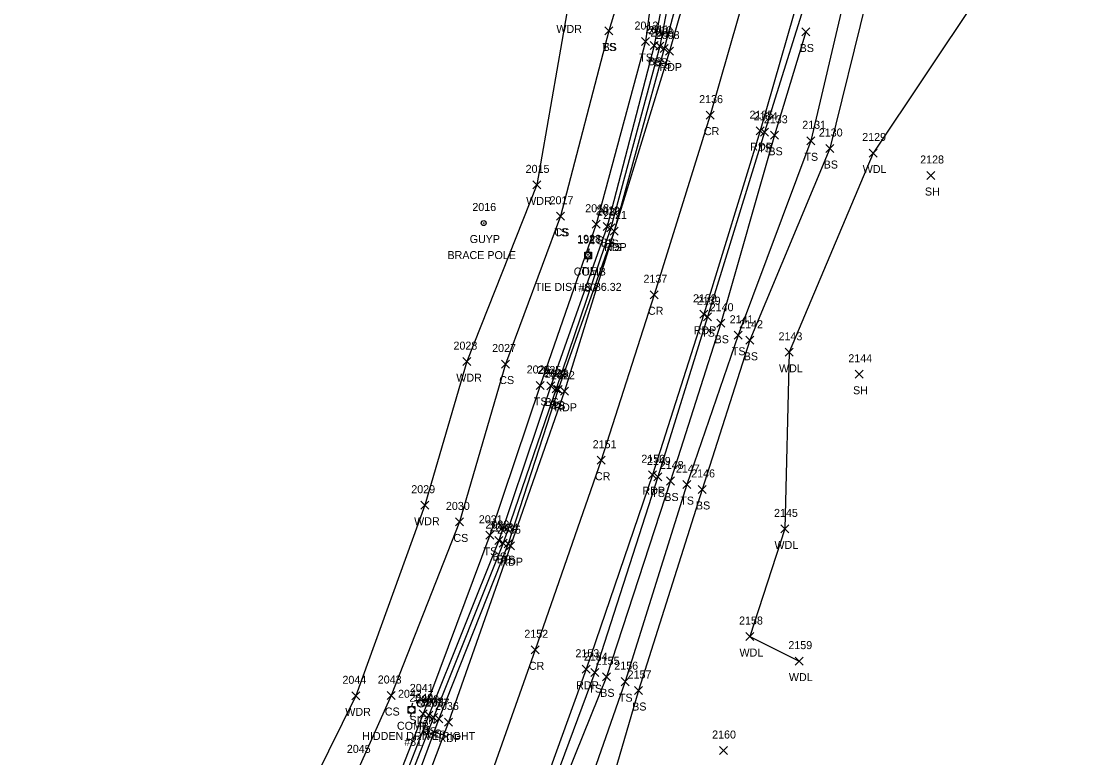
# Model space of a CAD drawing. Extents: x 1678863 to 1683592, y 407783 to 418211.
# Drawn here: x 1680931.7 to 1681197.9, y 416455.1 to 416639 of the extents above; entities that cross this region are included whole.
import ezdxf

# ---------------------------------------------------------------- set-up
doc = ezdxf.new("R2010")
doc.units = 0
for name, color, linetype in [('C_A', 7, 'Continuous'), ('C_C', 7, 'Continuous'), ('C_I', 7, 'Continuous'), ('CBP', 7, 'Continuous'), ('L_A', 7, 'Continuous'), ('L_I', 7, 'Continuous'), ('L_TIC', 7, 'Continuous'), ('LAWA', 7, 'Continuous'), ('LELB', 7, 'Continuous'), ('P_A', 7, 'Continuous'), ('P_I', 7, 'Continuous'), ('P_TIC', 7, 'Continuous'), ('PET', 7, 'Continuous'), ('PRC', 7, 'Continuous'), ('S_A', 7, 'Continuous'), ('S_C', 7, 'Continuous'), ('S_I', 7, 'Continuous'), ('SSGN', 7, 'Continuous'), ('U_A', 7, 'Continuous'), ('U_C', 7, 'Continuous'), ('U_I', 7, 'Continuous'), ('UP', 7, 'Continuous'), ('UPGW', 7, 'Continuous')]:
    doc.layers.add(name, color=color, linetype=linetype)

msp = doc.modelspace()

# ---------------------------------------------------------------- linework, layer by layer
at = {"layer": 'CBP'}
for radius in [0.625, 0.0833]:
    msp.add_circle((1681073.29, 416580.64), radius, dxfattribs=at)
at = {"layer": 'L_TIC'}
for points in [[(1681077.49, 416635.56), (1681079.49, 416637.56)], [(1681079.49, 416635.56), (1681077.49, 416637.56)], [(1681077.49, 416635.56), (1681079.49, 416637.56)], [(1681079.49, 416635.56), (1681077.49, 416637.56)], [(1681126.73, 416635.31), (1681128.73, 416637.31)], [(1681128.73, 416635.31), (1681126.73, 416637.31)], [(1681086.69, 416632.91), (1681088.69, 416634.91)], [(1681088.69, 416632.91), (1681086.69, 416634.91)], [(1681088.82, 416631.97), (1681090.82, 416633.97)], [(1681090.82, 416631.97), (1681088.82, 416633.97)], [(1681090.25, 416631.74), (1681092.25, 416633.74)], [(1681092.25, 416631.74), (1681090.25, 416633.74)], [(1681091.29, 416631.17), (1681093.29, 416633.17)], [(1681093.29, 416631.17), (1681091.29, 416633.17)], [(1681116.39, 416610.26), (1681118.39, 416612.26)], [(1681118.39, 416610.26), (1681116.39, 416612.26)], [(1681118.93, 416609.51), (1681120.93, 416611.51)], [(1681120.93, 416609.51), (1681118.93, 416611.51)], [(1681127.95, 416608.13), (1681129.95, 416610.13)], [(1681129.95, 416608.13), (1681127.95, 416610.13)], [(1681132.74, 416606.2), (1681134.74, 416608.2)], [(1681134.74, 416606.2), (1681132.74, 416608.2)], [(1681132.74, 416606.2), (1681134.74, 416608.2)], [(1681134.74, 416606.2), (1681132.74, 416608.2)], [(1681143.5, 416605.08), (1681145.5, 416607.08)], [(1681145.5, 416605.08), (1681143.5, 416607.08)], [(1681157.97, 416599.46), (1681159.97, 416601.46)], [(1681159.97, 416599.46), (1681157.97, 416601.46)], [(1681059.5, 416597.12), (1681061.5, 416599.12)], [(1681061.5, 416597.12), (1681059.5, 416599.12)], [(1681065.47, 416589.28), (1681067.47, 416591.28)], [(1681067.47, 416589.28), (1681065.47, 416591.28)], [(1681065.47, 416589.28), (1681067.47, 416591.28)], [(1681067.47, 416589.28), (1681065.47, 416591.28)], [(1681074.38, 416587.29), (1681076.38, 416589.29)], [(1681076.38, 416587.29), (1681074.38, 416589.29)], [(1681077.07, 416586.72), (1681079.07, 416588.72)], [(1681079.07, 416586.72), (1681077.07, 416588.72)], [(1681077.98, 416586.43), (1681079.98, 416588.43)], [(1681079.98, 416586.43), (1681077.98, 416588.43)], [(1681078.85, 416585.59), (1681080.85, 416587.59)], [(1681080.85, 416585.59), (1681078.85, 416587.59)], [(1681102.18, 416564.19), (1681104.18, 416566.19)], [(1681104.18, 416564.19), (1681102.18, 416566.19)], [(1681105.49, 416562.56), (1681107.49, 416564.56)], [(1681107.49, 416562.56), (1681105.49, 416564.56)], [(1681109.82, 416559.56), (1681111.82, 416561.56)], [(1681111.82, 416559.56), (1681109.82, 416561.56)], [(1681112.76, 416558.31), (1681114.76, 416560.31)], [(1681114.76, 416558.31), (1681112.76, 416560.31)], [(1681122.59, 416555.3), (1681124.59, 416557.3)], [(1681124.59, 416555.3), (1681122.59, 416557.3)], [(1681042.04, 416552.97), (1681044.04, 416554.97)], [(1681044.04, 416552.97), (1681042.04, 416554.97)], [(1681051.69, 416552.37), (1681053.69, 416554.37)], [(1681053.69, 416552.37), (1681051.69, 416554.37)], [(1681140.02, 416549.82), (1681142.02, 416551.82)], [(1681142.02, 416549.82), (1681140.02, 416551.82)], [(1681060.37, 416547.02), (1681062.37, 416549.02)], [(1681062.37, 416547.02), (1681060.37, 416549.02)], [(1681063.01, 416546.9), (1681065.01, 416548.9)], [(1681065.01, 416546.9), (1681063.01, 416548.9)], [(1681064.33, 416546.21), (1681066.33, 416548.21)], [(1681066.33, 416546.21), (1681064.33, 416548.21)], [(1681064.82, 416546), (1681066.82, 416548)], [(1681066.82, 416546), (1681064.82, 416548)], [(1681089.71, 416524.17), (1681091.71, 416526.17)], [(1681091.71, 416524.17), (1681089.71, 416526.17)], [(1681092.93, 416523.16), (1681094.93, 416525.16)], [(1681094.93, 416523.16), (1681092.93, 416525.16)], [(1681096.95, 416522.26), (1681098.95, 416524.26)], [(1681098.95, 416522.26), (1681096.95, 416524.26)], [(1681100.82, 416521.05), (1681102.82, 416523.05)], [(1681102.82, 416521.05), (1681100.82, 416523.05)], [(1681031.51, 416517.11), (1681033.51, 416519.11)], [(1681033.51, 416517.11), (1681031.51, 416519.11)], [(1681040.24, 416512.94), (1681042.24, 416514.94)], [(1681042.24, 416512.94), (1681040.24, 416514.94)], [(1681047.8, 416509.6), (1681049.8, 416511.6)], [(1681049.8, 416509.6), (1681047.8, 416511.6)], [(1681121.46, 416511.19), (1681123.46, 416513.19)], [(1681123.46, 416511.19), (1681121.46, 416513.19)], [(1681050.02, 416508.29), (1681052.02, 416510.29)], [(1681052.02, 416508.29), (1681050.02, 416510.29)], [(1681051.09, 416507.6), (1681053.09, 416509.6)], [(1681053.09, 416507.6), (1681051.09, 416509.6)], [(1681052.32, 416507.48), (1681054.32, 416509.48)], [(1681054.32, 416507.48), (1681052.32, 416509.48)], [(1681112.73, 416484.31), (1681114.73, 416486.31)], [(1681114.73, 416484.31), (1681112.73, 416486.31)], [(1681125.06, 416478.17), (1681127.06, 416480.17)], [(1681127.06, 416478.17), (1681125.06, 416480.17)], [(1681073.97, 416475.31), (1681075.97, 416477.31)], [(1681075.97, 416475.31), (1681073.97, 416477.31)], [(1681076.92, 416474.25), (1681078.92, 416476.25)], [(1681078.92, 416474.25), (1681076.92, 416476.25)], [(1681081.61, 416473.04), (1681083.61, 416475.04)], [(1681083.61, 416473.04), (1681081.61, 416475.04)], [(1681014.3, 416469.5), (1681016.3, 416471.5)], [(1681016.3, 416469.5), (1681014.3, 416471.5)], [(1681023.11, 416469.58), (1681025.11, 416471.58)], [(1681025.11, 416469.58), (1681023.11, 416471.58)], [(1681084.89, 416470.83), (1681086.89, 416472.83)], [(1681086.89, 416470.83), (1681084.89, 416472.83)], [(1681031.11, 416465.02), (1681033.11, 416467.02)], [(1681033.11, 416465.02), (1681031.11, 416467.02)], [(1681032.52, 416464.65), (1681034.52, 416466.65)], [(1681034.52, 416464.65), (1681032.52, 416466.65)], [(1681033.7, 416464.08), (1681035.7, 416466.08)], [(1681035.7, 416464.08), (1681033.7, 416466.08)], [(1681035.07, 416463.79), (1681037.07, 416465.79)], [(1681037.07, 416463.79), (1681035.07, 416465.79)], [(1681106.14, 416455.84), (1681108.14, 416457.84)], [(1681108.14, 416455.84), (1681106.14, 416457.84)]]:
    msp.add_lwpolyline(points, dxfattribs=at)
at = {"layer": 'LAWA'}
for points in [[(1681123.87, 416850.36), (1681112.64, 416799.22), (1681096.75, 416747.49), (1681084.37, 416698.19), (1681077.36, 416674.66), (1681068.03, 416641.07), (1681060.5, 416598.12), (1681043.04, 416553.97), (1681032.51, 416518.11), (1681015.3, 416470.5), (1680994.93, 416429.19), (1680981.71, 416387.43), (1680969.09, 416365.63), (1680956.12, 416364.06)], [(1681197.88, 416804.7), (1681183.57, 416753.88), (1681190.27, 416722.43), (1681186.67, 416700.64), (1681165.75, 416661.66), (1681170.52, 416645), (1681144.5, 416606.08), (1681123.59, 416556.3), (1681122.46, 416512.19), (1681113.73, 416485.31), (1681126.06, 416479.17)]]:
    msp.add_lwpolyline(points, dxfattribs=at)
at = {"layer": 'LELB'}
for points in [[(1681156.02, 416991.73), (1681158.77, 416971.49), (1681161.75, 416953.98), (1681162.32, 416941.7), (1681158.74, 416923.13), (1681154.13, 416896.13), (1681147.11, 416869.12), (1681139.06, 416835.21), (1681130.14, 416794.31), (1681117.24, 416738.31), (1681106.01, 416695.36), (1681091.21, 416662.1), (1681090.98, 416658.87), (1681087.69, 416633.91), (1681075.38, 416588.29), (1681061.37, 416548.02), (1681048.8, 416510.6), (1681032.11, 416466.02), (1681014.69, 416421.51), (1680996.26, 416391.39), (1680989.28, 416368.73)], [(1681149.59, 416868.75), (1681142.29, 416833.77), (1681132.86, 416793.93), (1681119.42, 416737.18), (1681108.02, 416695.19), (1681098.81, 416668.5), (1681096.71, 416664.36), (1681094.64, 416660.46), (1681094.42, 416657.6), (1681089.82, 416632.97), (1681078.07, 416587.72), (1681064.01, 416547.9), (1681051.02, 416509.29), (1681033.52, 416465.65), (1681016.06, 416420.72), (1681000.74, 416389.34), (1680998.23, 416385.31), (1680994.64, 416376.69), (1680989.07, 416359.69), (1680992.46, 416359.07)], [(1681150.8, 416868.4), (1681143.7, 416833.38), (1681134.26, 416793.51), (1681120.67, 416736.84), (1681109.84, 416694.34), (1681100.61, 416667.6), (1681097.91, 416664.11), (1681097.08, 416660.69), (1681095.87, 416657.34), (1681091.25, 416632.74), (1681078.98, 416587.43), (1681065.33, 416547.21), (1681052.09, 416508.6), (1681034.7, 416465.08), (1681017.14, 416420.01), (1681002.48, 416388.48), (1680999.77, 416381.75), (1680997.06, 416375.63), (1680992.46, 416359.07)], [(1681151.67, 416868.54), (1681144.5, 416832.96), (1681135.35, 416792.9), (1681121.88, 416736.5), (1681110.76, 416694.17), (1681101.65, 416666.79), (1681092.29, 416632.17), (1681079.85, 416586.59), (1681065.82, 416547), (1681053.32, 416508.48), (1681036.07, 416464.79), (1681019.24, 416419.35), (1681003.42, 416376.29), (1680994.23, 416357.71)], [(1681183.55, 416833.63), (1681182.26, 416826.66), (1681180.25, 416810.78), (1681169.29, 416761.59), (1681161.1, 416720.62), (1681142.83, 416670.76), (1681140.44, 416656.68), (1681135.09, 416652.62), (1681137.22, 416644.16), (1681128.95, 416609.13), (1681110.82, 416560.56), (1681097.95, 416523.26), (1681082.61, 416474.04), (1681065.03, 416423.77), (1681042.03, 416376.09), (1681025.29, 416329.55), (1681005.26, 416289.72), (1680988.66, 416250.32), (1680971.75, 416212.59), (1680955.51, 416173.95), (1680940.89, 416151.62), (1680938.9, 416140.82), (1680934.47, 416141.15), (1680931.74, 416141.56)], [(1681176.14, 416832.62), (1681170.47, 416807.9), (1681160.43, 416764.66), (1681148.59, 416720.54), (1681137.34, 416672.66), (1681130.15, 416651.97), (1681117.39, 416611.26), (1681103.18, 416565.19), (1681090.71, 416525.17), (1681074.97, 416476.31), (1681056.64, 416426.82), (1681038.03, 416377.84), (1681018.75, 416331.61)], [(1681165.97, 416718.74), (1681148.66, 416668.7), (1681146.23, 416653.37), (1681141.68, 416649.74), (1681142.8, 416644.03), (1681133.74, 416607.2)], [(1681096.41, 416695.15), (1681086.76, 416663.72), (1681078.49, 416636.56)], [(1681078.49, 416636.56), (1681066.47, 416590.28)], [(1681127.73, 416636.31), (1681119.93, 416610.51), (1681106.49, 416563.56), (1681093.93, 416524.16), (1681077.92, 416475.25), (1681058.1, 416426.11), (1681040.38, 416376.76), (1681020.53, 416330.9)], [(1681133.74, 416607.2), (1681113.76, 416559.31), (1681101.82, 416522.05), (1681085.89, 416471.83), (1681071.19, 416421.26), (1681051.86, 416373.86), (1681035.51, 416329.96), (1681028.19, 416324.2), (1681022.12, 416304.25), (1681026.28, 416298.9), (1681016.09, 416285.94), (1681000.34, 416247.72), (1680995.54, 416236.51), (1680975.32, 416181.38), (1680956.88, 416150.62)], [(1681066.47, 416590.28), (1681052.69, 416553.37), (1681041.24, 416513.94), (1681024.11, 416470.58), (1681016.4, 416453.26), (1681011.7, 416442.37), (1681008.55, 416423.6)]]:
    msp.add_lwpolyline(points, dxfattribs=at)
at = {"layer": 'P_TIC'}
for points in [[(1681092.64, 416630.55), (1681094.64, 416632.55)], [(1681094.64, 416630.55), (1681092.64, 416632.55)], [(1681102.82, 416614.54), (1681104.82, 416616.54)], [(1681104.82, 416614.54), (1681102.82, 416616.54)], [(1681115.34, 416610.65), (1681117.34, 416612.65)], [(1681117.34, 416610.65), (1681115.34, 416612.65)], [(1681078.85, 416585.59), (1681080.85, 416587.59)], [(1681080.85, 416585.59), (1681078.85, 416587.59)], [(1681088.85, 416569.67), (1681090.85, 416571.67)], [(1681090.85, 416569.67), (1681088.85, 416571.67)], [(1681101.21, 416564.8), (1681103.21, 416566.8)], [(1681103.21, 416564.8), (1681101.21, 416566.8)], [(1681066.41, 416545.57), (1681068.41, 416547.57)], [(1681068.41, 416545.57), (1681066.41, 416547.57)], [(1681075.6, 416528.35), (1681077.6, 416530.35)], [(1681077.6, 416528.35), (1681075.6, 416530.35)], [(1681088.4, 416524.72), (1681090.4, 416526.72)], [(1681090.4, 416524.72), (1681088.4, 416526.72)], [(1681052.93, 416507), (1681054.93, 416509)], [(1681054.93, 416507), (1681052.93, 416509)], [(1681059.09, 416480.99), (1681061.09, 416482.99)], [(1681061.09, 416480.99), (1681059.09, 416482.99)], [(1681071.85, 416476.14), (1681073.85, 416478.14)], [(1681073.85, 416476.14), (1681071.85, 416478.14)], [(1681037.48, 416462.96), (1681039.48, 416464.96)], [(1681039.48, 416462.96), (1681037.48, 416464.96)]]:
    msp.add_lwpolyline(points, dxfattribs=at)
at = {"layer": 'PET'}
for points in [[(1681153.18, 416868.37), (1681145.34, 416832.84), (1681136.15, 416792.61), (1681122.35, 416736.31), (1681111.4, 416694.04), (1681103.69, 416666.47), (1681093.64, 416631.55), (1681079.85, 416586.59), (1681067.41, 416546.57), (1681053.93, 416508), (1681038.48, 416463.96), (1681021.16, 416418.05), (1681004.81, 416375.74), (1680996.01, 416353.71), (1680982.81, 416321.51)], [(1681179.13, 416866.45), (1681171.86, 416831.02), (1681167.77, 416808.05), (1681157.66, 416765.3), (1681146.92, 416720.99), (1681134.47, 416674.25), (1681128.07, 416652.5), (1681116.34, 416611.65), (1681102.21, 416565.8), (1681089.4, 416525.72), (1681072.85, 416477.14), (1681054.83, 416427.43), (1681035.74, 416378.53), (1681017.06, 416332.68)]]:
    msp.add_lwpolyline(points, dxfattribs=at)
at = {"layer": 'PRC'}
msp.add_lwpolyline([(1681167.36, 416870.15), (1681159.37, 416832.34), (1681154.72, 416812.12), (1681150.38, 416792.5), (1681145.13, 416769.7), (1681134.02, 416724.02), (1681121.77, 416677.97), (1681115.56, 416656.52), (1681103.82, 416615.54), (1681089.85, 416570.67), (1681076.6, 416529.35), (1681060.09, 416481.99), (1681042.51, 416432.25), (1681023.42, 416383.55), (1681004.96, 416337.97)], dxfattribs=at)
at = {"layer": 'SSGN'}
for p, q in [((1681029.94, 416469.33), (1681033.27, 416469.33)), ((1681031.58, 416468.5), (1681031.58, 416468.5))]:
    msp.add_line(p, q, dxfattribs=at)
msp.add_circle((1681031.58, 416468.5), 0.833, dxfattribs=at)
at = {"layer": 'UP'}
for p, q in [((1681072.52, 416579.63), (1681072.52, 416581.3)), ((1681072.52, 416581.3), (1681074.18, 416581.3)), ((1681073.6, 416582.13), (1681073.35, 416581.3)), ((1681074.18, 416581.3), (1681074.18, 416579.63)), ((1681074.18, 416579.63), (1681072.52, 416579.63)), ((1681073.1, 416578.8), (1681073.35, 416579.63)), ((1681073.35, 416580.47), (1681073.35, 416580.47)), ((1681028.35, 416466.19), (1681028.35, 416467.86)), ((1681028.35, 416467.86), (1681030.02, 416467.86)), ((1681030.02, 416466.19), (1681028.35, 416466.19)), ((1681028.93, 416465.36), (1681029.18, 416466.19)), ((1681029.43, 416468.69), (1681029.18, 416467.86)), ((1681029.18, 416467.02), (1681029.18, 416467.02)), ((1681030.02, 416467.86), (1681030.02, 416466.19))]:
    msp.add_line(p, q, dxfattribs=at)
for centre in [(1681073.35, 416580.47), (1681029.18, 416467.02)]:
    msp.add_circle(centre, 0.833, dxfattribs=at)
at = {"layer": 'UPGW'}
for radius in [0.625, 0.0833]:
    msp.add_circle((1681047.24, 416588.59), radius, dxfattribs=at)

# ---------------------------------------------------------------- texts
at = {"layer": 'C_A'}
msp.add_text('TIE', height=2, dxfattribs=at).set_placement((1681071.37, 416575.64))
at = {"layer": 'C_C'}
msp.add_text('TIE DIST IS 86.32', height=2, dxfattribs=at).set_placement((1681060, 416571.64))
at = {"layer": 'C_I'}
msp.add_text('1928', height=2, dxfattribs=at).set_placement((1681070.6, 416583.64))
at = {"layer": 'L_A'}
for s, p in [('WDR', (1681065.4, 416636.07)), ('TS', (1681076.9, 416631.56)), ('BS', (1681076.93, 416631.56)), ('BS', (1681126.17, 416631.31)), ('TS', (1681086.1, 416628.91)), ('BS', (1681088.26, 416627.97)), ('BS', (1681089.69, 416627.74)), ('TS', (1681090.7, 416627.17)), ('TS', (1681115.8, 416606.26)), ('BS', (1681118.37, 416605.51)), ('TS', (1681127.36, 416604.13)), ('BS', (1681132.18, 416602.2)), ('BS', (1681132.18, 416602.2)), ('WDL', (1681141.92, 416601.08)), ('SH', (1681157.46, 416595.46)), ('WDR', (1681057.86, 416593.12)), ('TS', (1681064.88, 416585.28)), ('CS', (1681064.92, 416585.28)), ('TS', (1681073.79, 416583.29)), ('BS', (1681076.51, 416582.72)), ('BS', (1681077.42, 416582.43)), ('TS', (1681078.26, 416581.59)), ('TS', (1681101.59, 416560.19)), ('BS', (1681104.93, 416558.56)), ('TS', (1681109.23, 416555.56)), ('BS', (1681112.2, 416554.31)), ('WDL', (1681121.01, 416551.3)), ('WDR', (1681040.4, 416548.97)), ('CS', (1681051.13, 416548.37)), ('SH', (1681139.51, 416545.82)), ('TS', (1681059.78, 416543.02)), ('BS', (1681062.45, 416542.9)), ('BS', (1681063.77, 416542.21)), ('TS', (1681064.23, 416542)), ('TS', (1681089.12, 416520.17)), ('BS', (1681092.37, 416519.16)), ('TS', (1681096.36, 416518.26)), ('BS', (1681100.26, 416517.05)), ('WDR', (1681029.87, 416513.11)), ('CS', (1681039.68, 416508.94)), ('WDL', (1681119.88, 416507.19)), ('TS', (1681047.21, 416505.6)), ('BS', (1681049.46, 416504.29)), ('BS', (1681050.53, 416503.6)), ('TS', (1681051.73, 416503.48)), ('WDL', (1681111.15, 416480.31)), ('WDL', (1681123.48, 416474.17)), ('TS', (1681073.38, 416471.31)), ('BS', (1681076.36, 416470.25)), ('TS', (1681081.02, 416469.04)), ('BS', (1681084.33, 416466.83)), ('WDR', (1681012.67, 416465.5)), ('CS', (1681022.55, 416465.58)), ('TS', (1681030.52, 416461.02)), ('BS', (1681031.96, 416460.65)), ('BS', (1681033.14, 416460.08)), ('TS', (1681034.48, 416459.79))]:
    msp.add_text(s, height=2, dxfattribs=at).set_placement(p)
at = {"layer": 'L_I'}
for s, p in [('2012', (1681084.92, 416636.91)), ('2011', (1681087.62, 416635.97)), ('2010', (1681088.39, 416635.74)), ('2009', (1681088.87, 416635.17)), ('2134', (1681114.7, 416614.26)), ('2133', (1681117.24, 416613.51)), ('2131', (1681126.82, 416612.13)), ('2130', (1681130.96, 416610.2)), ('2130', (1681130.96, 416610.2)), ('2129', (1681141.8, 416609.08)), ('2128', (1681156.28, 416603.46)), ('2015', (1681057.72, 416601.12)), ('2017', (1681063.7, 416593.28)), ('2017', (1681063.7, 416593.28)), ('2018', (1681072.61, 416591.29)), ('2019', (1681075.29, 416590.72)), ('2020', (1681075.55, 416590.43)), ('2021', (1681077.07, 416589.59)), ('2139', (1681100.48, 416568.19)), ('2140', (1681103.71, 416566.56)), ('2141', (1681108.69, 416563.56)), ('2142', (1681111.07, 416562.31)), ('2143', (1681120.9, 416559.3)), ('2028', (1681039.7, 416556.97)), ('2027', (1681049.35, 416556.37)), ('2144', (1681138.33, 416553.82)), ('2026', (1681057.98, 416551.02)), ('2025', (1681060.67, 416550.9)), ('2024', (1681061.99, 416550.21)), ('2023', (1681062.48, 416550)), ('2149', (1681088.01, 416528.17)), ('2148', (1681091.24, 416527.16)), ('2147', (1681095.26, 416526.26)), ('2146', (1681099.08, 416525.05)), ('2029', (1681029.16, 416521.11)), ('2030', (1681037.81, 416516.94)), ('2145', (1681119.77, 416515.19)), ('2031', (1681046.03, 416513.6)), ('2032', (1681047.68, 416512.29)), ('2033', (1681048.75, 416511.6)), ('2034', (1681049.98, 416511.48)), ('2158', (1681111.04, 416488.31)), ('2159', (1681123.36, 416482.17)), ('2154', (1681072.27, 416479.31)), ('2155', (1681075.23, 416478.25)), ('2156', (1681079.87, 416477.04)), ('2157', (1681083.19, 416474.83)), ('2044', (1681011.96, 416473.5)), ('2043', (1681020.78, 416473.58)), ('2040', (1681028.68, 416469.02)), ('2039', (1681030.17, 416468.65)), ('2038', (1681031.36, 416468.08)), ('2037', (1681032.73, 416467.79)), ('2160', (1681104.31, 416459.84)), ('2045', (1681013.06, 416456.26))]:
    msp.add_text(s, height=2, dxfattribs=at).set_placement(p)
at = {"layer": 'P_A'}
for s, p in [('RDP', (1681091.13, 416626.55)), ('CR', (1681102.25, 416610.54)), ('RDP', (1681113.83, 416606.65)), ('RDP', (1681077.33, 416581.59)), ('CR', (1681088.28, 416565.67)), ('RDP', (1681099.7, 416560.8)), ('RDP', (1681064.9, 416541.57)), ('CR', (1681075.03, 416524.35)), ('RDP', (1681086.89, 416520.72)), ('RDP', (1681051.42, 416503)), ('CR', (1681058.52, 416476.99)), ('RDP', (1681070.34, 416472.14)), ('RDP', (1681035.97, 416458.96))]:
    msp.add_text(s, height=2, dxfattribs=at).set_placement(p)
at = {"layer": 'P_I'}
for s, p in [('2008', (1681090.22, 416634.55)), ('2136', (1681101.07, 416618.54)), ('2135', (1681113.65, 416614.65)), ('2021', (1681077.07, 416589.59)), ('2137', (1681087.16, 416573.67)), ('2138', (1681099.52, 416568.8)), ('2022', (1681064.07, 416549.57)), ('2151', (1681074.47, 416532.35)), ('2150', (1681086.62, 416528.72)), ('2035', (1681050.6, 416511)), ('2152', (1681057.39, 416484.99)), ('2153', (1681070.16, 416480.14)), ('2036', (1681035.08, 416466.96))]:
    msp.add_text(s, height=2, dxfattribs=at).set_placement(p)
at = {"layer": 'S_A'}
msp.add_text('SIGN', height=2, dxfattribs=at).set_placement((1681028.72, 416463.48))
at = {"layer": 'S_C'}
msp.add_text('HIDDEN DRIVE RIGHT', height=2, dxfattribs=at).set_placement((1681016.9, 416459.48))
at = {"layer": 'S_I'}
msp.add_text('2041', height=2, dxfattribs=at).set_placement((1681028.79, 416471.48))
at = {"layer": 'U_A'}
for s, p in [('GUYP', (1681043.75, 416583.59)), ('COMB', (1681069.74, 416575.47)), ('COMB', (1681025.57, 416462.02))]:
    msp.add_text(s, height=2, dxfattribs=at).set_placement(p)
at = {"layer": 'U_C'}
for s, p in [('BRACE POLE', (1681038.2, 416579.59)), ('#80', (1681070.9, 416571.47)), ('#81', (1681027.39, 416458.02))]:
    msp.add_text(s, height=2, dxfattribs=at).set_placement(p)
at = {"layer": 'U_I'}
for s, p in [('2016', (1681044.41, 416591.59)), ('1927', (1681070.66, 416583.47)), ('2042', (1681025.84, 416470.02))]:
    msp.add_text(s, height=2, dxfattribs=at).set_placement(p)

doc.saveas('drawing.dxf')
